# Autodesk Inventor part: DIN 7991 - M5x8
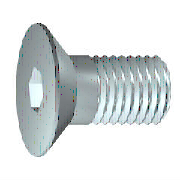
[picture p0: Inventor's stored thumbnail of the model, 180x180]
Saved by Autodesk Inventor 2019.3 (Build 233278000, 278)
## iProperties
Created: 2018-01
Part Number: DIN 7991 - M5x8
Material: Ocel, měkká
Description: Šrouby se zapuštěnou hlavou s vnitřním šestihranem
Document SubType Name: Modeling
Standard: DIN 7991
Designer: B-hon
Standards Organization: DIN
Language: cs-CZ
Size Designation: M5x8
Categories: <MemberInstance><Categories><Category DisplayName="Spojovací materiál" InternalName="e4da775c-781d-43d5-af7c-5136215cf5a6" Mnemonic="FSTN"><Category DisplayName
Density: 7.85 g/cm^3
Appearance: Pololeštěná
IsCustomPart: 0
Author: B-hon
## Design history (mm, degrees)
node "WorkPoint1"
sketch "Náčrt2"
  geometry: L1 (-2.5, -8)-(0, -8); L2 (-2.5, -2.8)-(-2.5, -8); L3 (-5, -0.3)-(-2.5, -2.8); L4 (-5, 0)-(-5, -0.3); L5 (0, 0)-(-5, 0); L6 (0, -8)-(0, 0); L7 (0, -8)-(0, 0); L8 (0, -9.6)-(0, 1.6) reference; L9 (1, 0)-(-6, 0) reference
  constraints: 14 end point, 3 vertical, 2 horizontal
  dimensions: "d3" = 5 distance of L5.start L4.start (= 0.5 x dk); "d5" = 2.5 distance of L1.start L1.end (= 0.5 x NND); "d7" = 8 distance of L1.end L5.start (= NLG); "ParC" = 0.3 distance of L4.start L3.start; "d22" = 0 distance between parallel lines of L8 L6; "d23" = 0 distance between parallel lines of L9 L5; "d43" = 45 deg angle of L6 L3 (= 0.5 x ang)
node "MSC_A1"
node "MSC_PF1"
node "MSC_PT1"
body "Solid1"
node "Náčrt1"
revolve "Rotace1" stored, may be unused: angle "d8" = 360 deg
sketch "Náčrt3"
  geometry: L1 (-1.5, 0.866)-(-1.5, -0.866); L2 (0, 1.732)-(-1.5, 0.866); L3 (1.5, 0.866)-(0, 1.732); L4 (1.5, -0.866)-(1.5, 0.866); L5 (0, -1.732)-(1.5, -0.866); L6 (-1.5, -0.866)-(0, -1.732); C1 r 1.5 at (0, 0); C2 r 2.5 at (0, 0) reference
  constraints: 12 end point, 6 tangent, 2 parallel, 2 vertical, 1 centre point, 1 concentric
  dimensions: "d11" = 3 diameter of C1 (= ParS); "d13" = 120 deg angle of L1 L2; "d15" = 120 deg angle of L6 L1
extrude "Vysunutí1" cut sketch "Náčrt3" distance "d16" = 2.3 (= ParT); taper "d17" = 0 deg
fillet "Zaoblení1" dims "d18" = 0.2 (= r)
chamfer "Zkosení1" distance "d19" = 0.4 (= 0.5 x PTC); stored, may be unused: angle "d20" = 45 deg, second distance "d39" = 0.4 (= 0.5 x PTC)
feature "Závit1" dims "d35" = 0, "b" = 3.6
other parameters: "NND" = 5 [user parameter; used in 2 equation terms], "PTC" = 0.8 [user parameter; used in 2 equation terms], "ParK" = 2.8 [user parameter], "ParS" = 3 [user parameter; used in 1 equation term], "ParT" = 2.3 [user parameter; used in 1 equation term], "r" = 0.2 [user parameter; used in 1 equation term], "NLG" = 8 [user parameter; used in 1 equation term], "d0" = 45 deg (derived), "d2" = 3 (derived), "d4" = 1.5 (derived), "d6" = 8 (derived), "d9" = 0, "d10" = 2 (derived), "d12" = 120 deg (derived), "d14" = 120 deg (derived), "d37" = 0, "d38" = 0, "d40" = 0, "d41" = 0, "d42" = 0, "ang" = 90 deg [user parameter; used in 1 equation term], "THREADDIA" = 5 (= NND) [user parameter]
